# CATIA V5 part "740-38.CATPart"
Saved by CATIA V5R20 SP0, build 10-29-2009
Part number: 740-38
Bounding box of the stored display mesh (mm): x -32.9 to 32.9, y -31 to 32.9, z -37 to 15
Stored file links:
  C:\Users\Utente\Desktop\IO LAVORO\3D X SITO CF\X SITO\740\740-38.CATPart
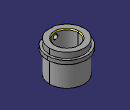
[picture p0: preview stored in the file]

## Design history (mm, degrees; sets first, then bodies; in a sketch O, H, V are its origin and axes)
Set1
  DatumSurface1 to DatumSurface35 "740-38"
Body1 (main body)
